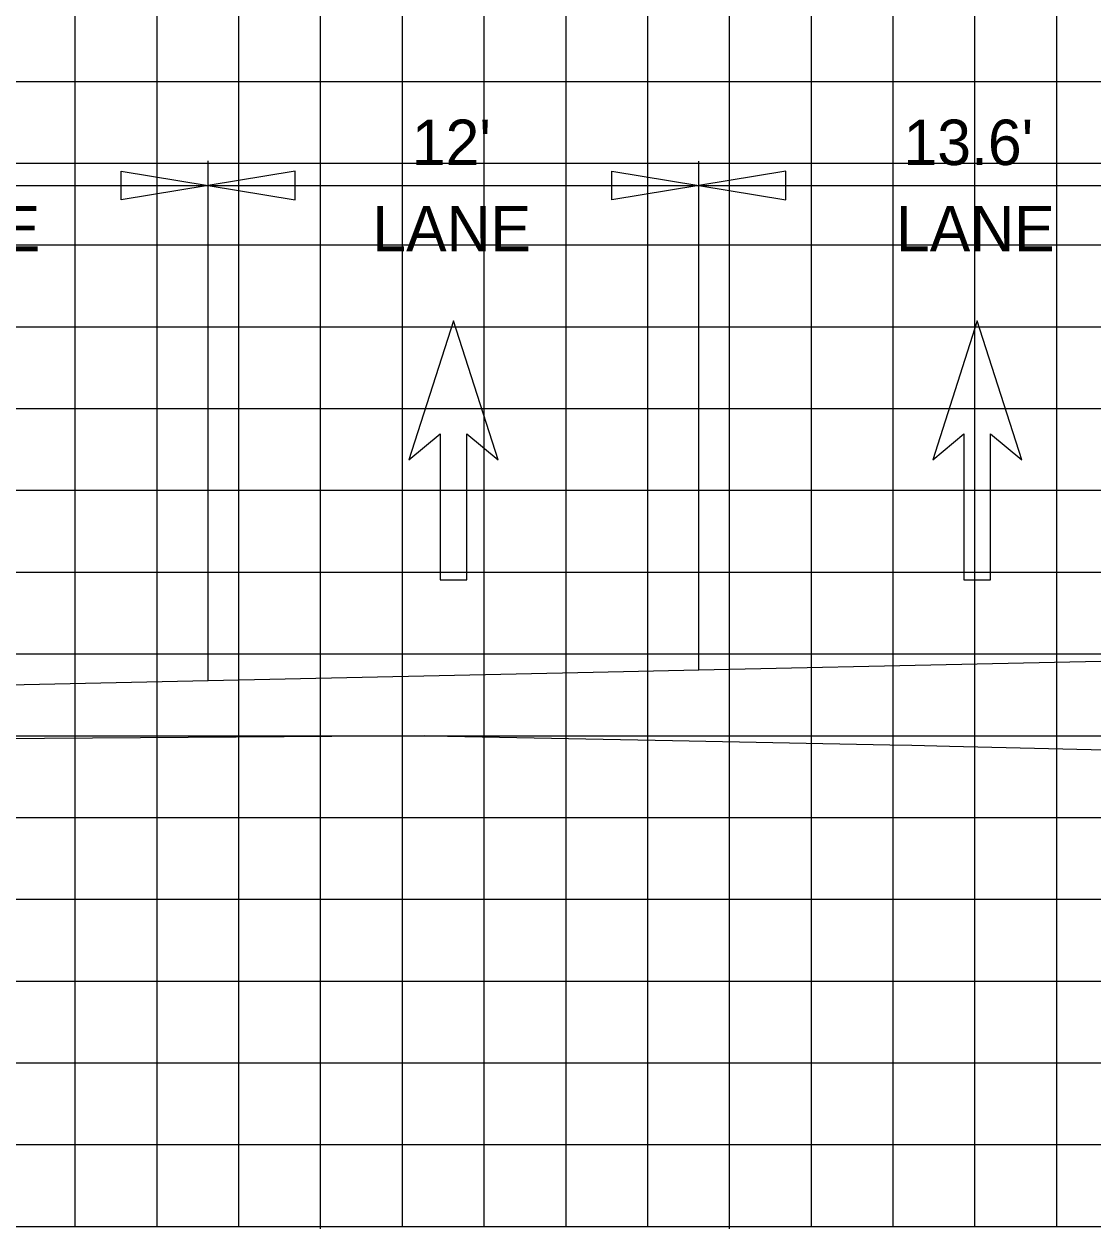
# Model space of a CAD drawing. Extents: x 1797809 to 2198143, y 249608 to 1237864.
# Drawn here: x 2195700.54 to 2195726.67, y 1237163.05 to 1237192.51 of the extents above; entities that cross this region are included whole.
import ezdxf

# ---------------------------------------------------------------- set-up
doc = ezdxf.new("R2010")
doc.units = 0
for name, color, linetype in [('3', 7, 'Continuous'), ('60', 7, 'Continuous'), ('DESIGN - SHEET - Light Grid', 7, 'Continuous'), ('DESIGN - TRAFFIC CONTROL PERMANENT - Signs', 7, 'Continuous'), ('GSDIMS', 7, 'Continuous'), ('GSSHT', 7, 'Continuous'), ('Level 28', 7, 'Continuous'), ('Level 55', 7, 'Continuous')]:
    doc.layers.add(name, color=color, linetype=linetype)

msp = doc.modelspace()

# ---------------------------------------------------------------- linework, layer by layer
at = {"layer": '3'}
for p, q in [((2195705.037, 1237176.457), (2195705.037, 1237189.162)), ((2195717.037, 1237176.715), (2195717.037, 1237189.156))]:
    msp.add_line(p, q, dxfattribs=at)
at = {"layer": '60'}
for p, q in [((2195657.787, 1237163.106), (2195787.787, 1237163.106)), ((2195707.787, 1237163.046), (2195707.787, 1237163.106)), ((2195717.787, 1237163.046), (2195717.787, 1237163.106))]:
    msp.add_line(p, q, dxfattribs=at)
at = {"layer": 'DESIGN - SHEET - Light Grid'}
msp.add_lwpolyline([(2195657.787, 1237174.595), (2195658.845, 1237174.571), (2195659.91, 1237174.502), (2195660.089, 1237174.492), (2195660.504, 1237174.473), (2195663.264, 1237174.34), (2195663.831, 1237174.34), (2195670.107, 1237174.345), (2195673.042, 1237174.469), (2195673.596, 1237174.491), (2195674.692, 1237174.534), (2195674.847, 1237174.54), (2195677.95, 1237174.603), (2195686.428, 1237174.773), (2195693.523, 1237174.914), (2195698.688, 1237175.026), (2195709.231, 1237175.1), (2195710.338, 1237175.108), (2195710.888, 1237175.097), (2195716.393, 1237174.989), (2195721.708, 1237174.885), (2195722.245, 1237174.874), (2195723.166, 1237174.852), (2195735.286, 1237174.563)], dxfattribs=at)
at = {"layer": 'DESIGN - TRAFFIC CONTROL PERMANENT - Signs'}
msp.add_lwpolyline([(2195660.17, 1237175.34), (2195666.017, 1237175.541), (2195669.761, 1237175.691), (2195681.762, 1237175.955), (2195693.037, 1237176.198), (2195705.037, 1237176.457), (2195714.45, 1237176.66), (2195717.037, 1237176.715), (2195730.646, 1237177.009), (2195731.643, 1237176.969), (2195731.677, 1237176.936), (2195731.717, 1237176.896), (2195740.647, 1237176.539), (2195742.647, 1237176.459), (2195743.525, 1237176.424), (2195746.147, 1237176.319), (2195746.15, 1237176.318), (2195762.036, 1237171.022)], dxfattribs=at)
at = {"layer": 'GSDIMS'}
for p, q in [((2195693.037, 1237188.559), (2195705.037, 1237188.559)), ((2195705.037, 1237188.559), (2195717.037, 1237188.559)), ((2195717.037, 1237188.559), (2195730.646, 1237188.559))]:
    msp.add_line(p, q, dxfattribs=at)
for points in [[(2195705.037, 1237188.559), (2195702.909, 1237188.212), (2195702.909, 1237188.907)], [(2195705.037, 1237188.559), (2195707.165, 1237188.212), (2195707.165, 1237188.907)], [(2195717.037, 1237188.559), (2195714.909, 1237188.212), (2195714.909, 1237188.907)], [(2195717.037, 1237188.559), (2195719.166, 1237188.212), (2195719.166, 1237188.907)]]:
    msp.add_lwpolyline(points, close=True, dxfattribs=at)
at = {"layer": 'GSSHT'}
for p, q in [((2195701.787, 1237163.106), (2195701.787, 1237223.106)), ((2195703.787, 1237163.106), (2195703.787, 1237223.106)), ((2195705.787, 1237163.106), (2195705.787, 1237223.106)), ((2195707.787, 1237163.106), (2195707.787, 1237223.106)), ((2195709.787, 1237163.106), (2195709.787, 1237223.106)), ((2195711.787, 1237163.106), (2195711.787, 1237223.106)), ((2195713.787, 1237163.106), (2195713.787, 1237223.106)), ((2195715.787, 1237163.106), (2195715.787, 1237223.106)), ((2195717.787, 1237163.106), (2195717.787, 1237223.106)), ((2195719.787, 1237163.106), (2195719.787, 1237223.106)), ((2195721.787, 1237163.106), (2195721.787, 1237223.106)), ((2195723.787, 1237163.106), (2195723.787, 1237223.106)), ((2195725.787, 1237163.106), (2195725.787, 1237223.106)), ((2195657.787, 1237191.106), (2195787.787, 1237191.106)), ((2195657.787, 1237189.106), (2195787.787, 1237189.106)), ((2195657.787, 1237187.106), (2195787.787, 1237187.106)), ((2195657.787, 1237185.106), (2195787.787, 1237185.106)), ((2195657.787, 1237183.106), (2195787.787, 1237183.106)), ((2195657.787, 1237181.106), (2195787.787, 1237181.106)), ((2195657.787, 1237179.106), (2195787.787, 1237179.106)), ((2195657.787, 1237177.106), (2195787.787, 1237177.106)), ((2195657.787, 1237175.106), (2195787.787, 1237175.106)), ((2195657.787, 1237173.106), (2195787.787, 1237173.106)), ((2195657.787, 1237171.106), (2195787.787, 1237171.106)), ((2195657.787, 1237169.106), (2195787.787, 1237169.106)), ((2195657.787, 1237167.106), (2195787.787, 1237167.106)), ((2195657.787, 1237165.106), (2195787.787, 1237165.106)), ((2195657.787, 1237163.106), (2195787.787, 1237163.106))]:
    msp.add_line(p, q, dxfattribs=at)
at = {"layer": 'Level 28'}
for p, q in [((2195711.037, 1237185.25), (2195709.948, 1237181.852)), ((2195712.126, 1237181.852), (2195711.037, 1237185.25)), ((2195723.842, 1237185.25), (2195722.753, 1237181.852)), ((2195724.931, 1237181.852), (2195723.842, 1237185.25)), ((2195709.948, 1237181.852), (2195710.71, 1237182.491)), ((2195710.71, 1237182.491), (2195710.71, 1237178.92)), ((2195711.364, 1237178.92), (2195711.364, 1237182.491)), ((2195711.364, 1237182.491), (2195712.126, 1237181.852)), ((2195722.753, 1237181.852), (2195723.515, 1237182.491)), ((2195723.515, 1237182.491), (2195723.515, 1237178.92)), ((2195724.169, 1237178.92), (2195724.169, 1237182.491)), ((2195724.169, 1237182.491), (2195724.931, 1237181.852)), ((2195710.71, 1237178.92), (2195711.364, 1237178.92)), ((2195723.515, 1237178.92), (2195724.169, 1237178.92))]:
    msp.add_line(p, q, dxfattribs=at)

# ---------------------------------------------------------------- texts
at = {"layer": 'Level 55'}
for s, p in [("12'", (2195710.016, 1237189.059)), ("13.6'", (2195722.038, 1237189.059)), ('LANE', (2195697.051, 1237186.949)), ('LANE', (2195709.052, 1237186.949)), ('LANE', (2195721.856, 1237186.949))]:
    msp.add_text(s, height=1.1105, dxfattribs=at).set_placement(p)

doc.saveas('drawing.dxf')
